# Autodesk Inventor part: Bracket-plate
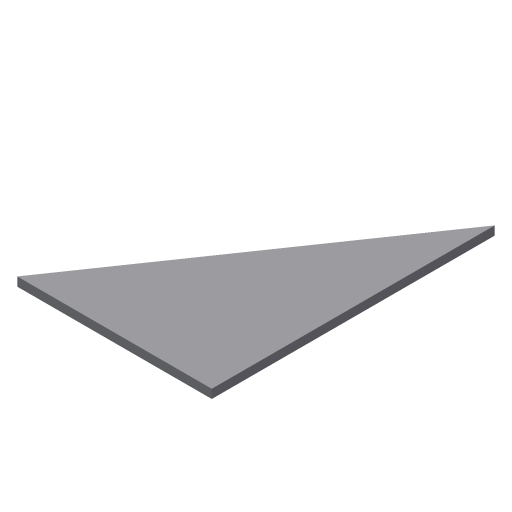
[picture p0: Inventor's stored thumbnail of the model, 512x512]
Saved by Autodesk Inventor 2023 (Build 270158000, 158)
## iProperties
Part Number: Bracket-plate
Document SubType Name: Modeling
Created: 2003-01
Designer: Owner
Density: 1 g/cm^3
Material: Generic
Appearance: Default
Control State: 0
Master: False
Checked Out: False
Shininess: 64.0
Length Units: 11269
Angle Units: 11279
Time Units: 11290
Mass Units: 11283
Length Display Precision: 3
Angle Display Precision: 2
Compacted: True
Density: 0.0
Volumn: 0.0
Area: 0.0
PropertySet Name: Model Information
Author: Owner
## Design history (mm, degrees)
sketch "Sketch1"
  geometry: L1 (-27.627, 0.004)-(-0.127, 0.004); L2 (-0.127, 0.004)-(-0.127, 40.004); L3 (-0.127, 40.004)-(-27.627, 0.004)
  constraints: 6 end point, 1 horizontal, 1 perpendicular
  dimensions: "d0" = 27.5 distance of L1.start L1.end; "d1" = 40 distance of L1.end L2.end
extrude "Extrusion1" new body sketch "Sketch1" distance "d2" = 1.25; taper "d3" = 0 deg
body "Solid1"
